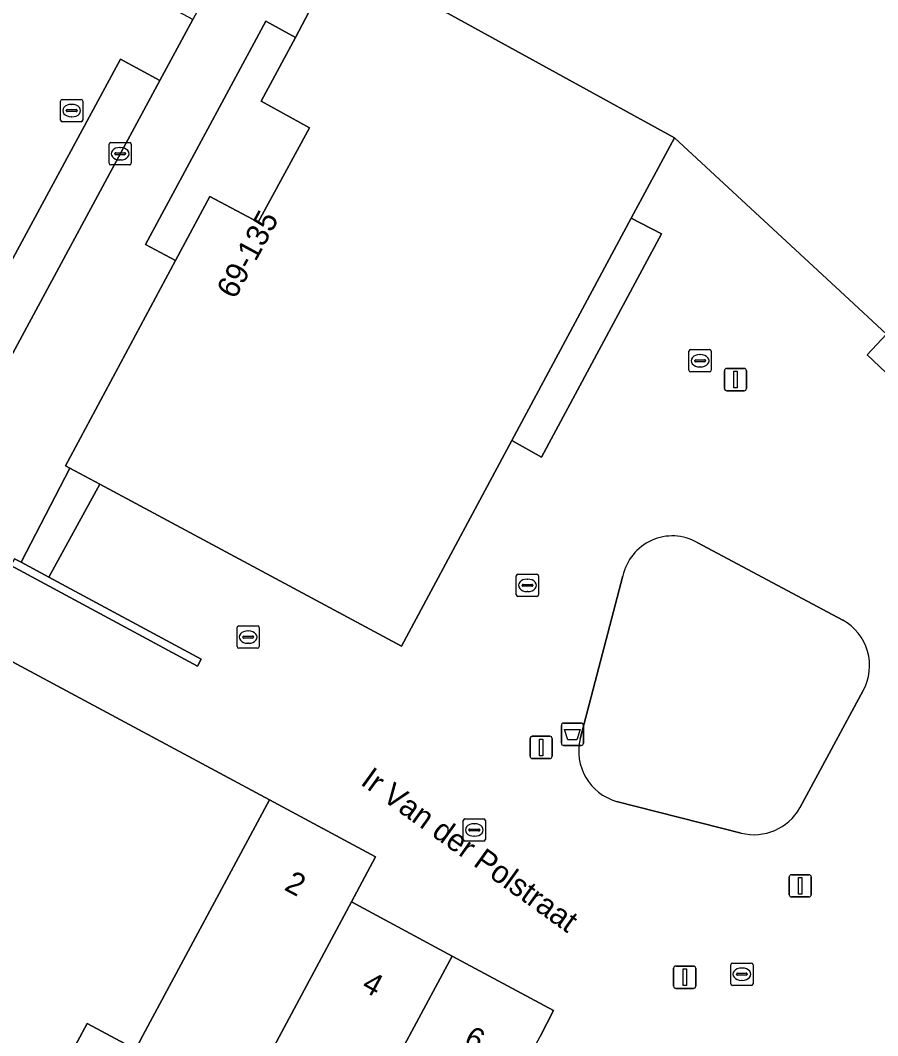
# Model space of a CAD drawing. Extents: x 159489 to 160304, y 383825 to 384531.
# Drawn here: x 159768.87 to 159807.43, y 384093.22 to 384138.89 of the extents above; entities that cross this region are included whole.
import ezdxf

# ---------------------------------------------------------------- set-up
doc = ezdxf.new("R2010")
doc.units = 0
for name, color, linetype in [('IMGEO_Afvalbak', 7, 'Continuous'), ('IMGEO_Erf', 7, 'Continuous'), ('IMGEO_Groenvoorziening', 7, 'Continuous'), ('IMGEO_Kolk', 7, 'Continuous'), ('IMGEO_Lichtmast', 7, 'Continuous'), ('IMGEO_Muur', 7, 'Continuous'), ('IMGEO_Openbare_ruimte_label', 7, 'Continuous'), ('IMGEO_Pand', 7, 'Continuous'), ('IMGEO_Pand_nummerreeks', 7, 'Continuous'), ('IMGEO_Pand_overbouw', 7, 'Continuous'), ('IMGEO_Parkeervlak_gesloten', 7, 'Continuous'), ('IMGEO_Rijbaan_lokaal_gesloten', 7, 'Continuous'), ('IMGEO_Rioolput', 7, 'Continuous'), ('IMGEO_Voetpad_open', 7, 'Continuous')]:
    doc.layers.add(name, color=color, linetype=linetype)

msp = doc.modelspace()

# ---------------------------------------------------------------- linework, layer by layer
at = {"layer": 'IMGEO_Afvalbak'}
for p, q in [((159793.2, 384106.378), (159793.2, 384107.178)), ((159793.2, 384107.178), (159793.2, 384106.378)), ((159793.3, 384107.278), (159794.09, 384107.278)), ((159794.09, 384107.278), (159793.3, 384107.278)), ((159794.19, 384107.178), (159794.19, 384106.378)), ((159794.19, 384106.378), (159794.19, 384107.178)), ((159794.09, 384106.278), (159793.3, 384106.278)), ((159793.3, 384106.278), (159794.09, 384106.278))]:
    msp.add_line(p, q, dxfattribs=at)
msp.add_lwpolyline([(159793.343, 384106.992), (159794.047, 384106.992), (159793.898, 384106.522), (159793.492, 384106.522), (159793.343, 384106.992)], dxfattribs=at)
for centre, start, end in [((159793.3, 384107.178), 90, 180), ((159793.3, 384107.178), 90, 180), ((159794.09, 384107.178), 0, 90), ((159794.09, 384107.178), 360, 90), ((159793.3, 384106.378), 180, 270), ((159793.3, 384106.378), 180, 270), ((159794.09, 384106.378), 270, 0), ((159794.09, 384106.378), 270, 0)]:
    msp.add_arc(centre, 0.1, start, end, dxfattribs=at)
at = {"layer": 'IMGEO_Erf'}
msp.add_lwpolyline([(159773.584, 384092.86), (159771.882, 384093.775), (159768.398, 384087.297)], dxfattribs=at)
at = {"layer": 'IMGEO_Groenvoorziening'}
for points in [[(159805.852, 384111.908), (159799.312, 384115.406)], [(159795.969, 384113.899), (159794.052, 384106.576)], [(159803.924, 384103.465), (159806.774, 384108.74)], [(159795.687, 384103.761), (159801.284, 384102.333)]]:
    msp.add_lwpolyline(points, dxfattribs=at)
for centre, radius, start, end in [((159798.195, 384113.423), 2.276, 60.5947, 167.9364), ((159804.736, 384109.865), 2.328, 331.1022, 61.3515), ((159796.32, 384106.011), 2.338, 166.0161, 254.2814), ((159801.862, 384104.63), 2.368, 255.8778, 330.5404)]:
    msp.add_arc(centre, radius, start, end, dxfattribs=at)
at = {"layer": 'IMGEO_Kolk'}
for p, q in [((159772.935, 384133.386), (159773.787, 384133.386)), ((159772.86, 384132.46), (159772.86, 384133.312)), ((159773.119, 384132.88), (159773.119, 384132.892)), ((159773.162, 384132.929), (159773.56, 384132.929)), ((159773.348, 384133.166), (159773.373, 384133.166)), ((159773.603, 384132.892), (159773.603, 384132.88)), ((159773.861, 384133.312), (159773.861, 384132.46)), ((159773.557, 384132.843), (159773.159, 384132.843)), ((159773.371, 384132.606), (159773.346, 384132.606)), ((159773.787, 384132.386), (159772.935, 384132.386)), ((159798.939, 384123.15), (159798.939, 384124.002)), ((159799.014, 384124.076), (159799.866, 384124.076)), ((159799.427, 384123.856), (159799.452, 384123.856)), ((159799.94, 384124.002), (159799.94, 384123.15)), ((159799.198, 384123.57), (159799.198, 384123.582)), ((159799.636, 384123.533), (159799.238, 384123.533)), ((159799.241, 384123.619), (159799.639, 384123.619)), ((159799.45, 384123.296), (159799.425, 384123.296)), ((159799.682, 384123.582), (159799.682, 384123.57)), ((159799.866, 384123.076), (159799.014, 384123.076)), ((159791.175, 384113.049), (159791.175, 384113.901)), ((159791.25, 384113.975), (159792.102, 384113.975)), ((159791.663, 384113.755), (159791.688, 384113.755)), ((159792.176, 384113.901), (159792.176, 384113.049)), ((159791.434, 384113.469), (159791.434, 384113.481)), ((159791.872, 384113.432), (159791.474, 384113.432)), ((159791.477, 384113.518), (159791.875, 384113.518)), ((159791.918, 384113.481), (159791.918, 384113.469)), ((159792.102, 384112.975), (159791.25, 384112.975)), ((159791.686, 384113.195), (159791.661, 384113.195)), ((159778.616, 384110.723), (159778.616, 384111.575)), ((159778.691, 384111.649), (159779.543, 384111.649)), ((159779.104, 384111.429), (159779.129, 384111.429)), ((159779.617, 384111.575), (159779.617, 384110.723)), ((159778.875, 384111.143), (159778.875, 384111.155)), ((159779.313, 384111.106), (159778.915, 384111.106)), ((159778.918, 384111.192), (159779.316, 384111.192)), ((159779.359, 384111.155), (159779.359, 384111.143)), ((159779.543, 384110.649), (159778.691, 384110.649)), ((159779.127, 384110.869), (159779.102, 384110.869)), ((159788.785, 384102.048), (159788.785, 384102.9)), ((159788.86, 384102.974), (159789.712, 384102.974)), ((159789.273, 384102.754), (159789.298, 384102.754)), ((159789.786, 384102.9), (159789.786, 384102.048)), ((159789.044, 384102.468), (159789.044, 384102.48)), ((159789.482, 384102.431), (159789.084, 384102.431)), ((159789.087, 384102.517), (159789.485, 384102.517)), ((159789.528, 384102.48), (159789.528, 384102.468)), ((159789.712, 384101.974), (159788.86, 384101.974)), ((159789.296, 384102.194), (159789.271, 384102.194)), ((159800.819, 384095.561), (159800.819, 384096.413)), ((159800.894, 384096.487), (159801.746, 384096.487)), ((159801.82, 384096.413), (159801.82, 384095.561)), ((159801.078, 384095.981), (159801.078, 384095.993)), ((159801.516, 384095.944), (159801.118, 384095.944)), ((159801.121, 384096.03), (159801.519, 384096.03)), ((159801.307, 384096.267), (159801.332, 384096.267)), ((159801.562, 384095.993), (159801.562, 384095.981)), ((159801.746, 384095.487), (159800.894, 384095.487)), ((159801.33, 384095.707), (159801.305, 384095.707))]:
    msp.add_line(p, q, dxfattribs=at)
for points in [[(159772.935, 384133.386), (159773.787, 384133.386)], [(159772.86, 384132.46), (159772.86, 384133.312)], [(159773.861, 384133.312), (159773.861, 384132.46)], [(159773.787, 384132.386), (159772.935, 384132.386)], [(159798.939, 384123.15), (159798.939, 384124.002)], [(159799.014, 384124.076), (159799.866, 384124.076)], [(159799.94, 384124.002), (159799.94, 384123.15)], [(159799.866, 384123.076), (159799.014, 384123.076)], [(159791.175, 384113.049), (159791.175, 384113.901)], [(159791.25, 384113.975), (159792.102, 384113.975)], [(159792.176, 384113.901), (159792.176, 384113.049)], [(159792.102, 384112.975), (159791.25, 384112.975)], [(159778.616, 384110.723), (159778.616, 384111.575)], [(159778.691, 384111.649), (159779.543, 384111.649)], [(159779.617, 384111.575), (159779.617, 384110.723)], [(159779.543, 384110.649), (159778.691, 384110.649)], [(159788.785, 384102.048), (159788.785, 384102.9)], [(159788.86, 384102.974), (159789.712, 384102.974)], [(159789.786, 384102.9), (159789.786, 384102.048)], [(159789.712, 384101.974), (159788.86, 384101.974)], [(159800.819, 384095.561), (159800.819, 384096.413)], [(159800.894, 384096.487), (159801.746, 384096.487)], [(159801.82, 384096.413), (159801.82, 384095.561)], [(159801.746, 384095.487), (159800.894, 384095.487)]]:
    msp.add_lwpolyline(points, dxfattribs=at)
for centre, radius, start, end in [((159772.937, 384133.31), 0.0765, 91.552, 178.448), ((159772.937, 384133.31), 0.0765, 91.552, 178.448), ((159773.785, 384133.31), 0.0765, 1.552, 88.448), ((159773.785, 384133.31), 0.0765, 1.552, 88.448), ((159773.159, 384132.889), 0.0403, 85.8775, 175.7526), ((159773.156, 384132.879), 0.0366, 178.938, 274.7102), ((159773.56, 384132.886), 0.043, 264.8664, 352.4533), ((159773.564, 384132.891), 0.0386, 1.7309, 96.639), ((159772.937, 384132.462), 0.0765, 181.552, 268.448), ((159772.937, 384132.462), 0.0765, 181.552, 268.448), ((159773.785, 384132.462), 0.0765, 271.552, 358.448), ((159773.785, 384132.462), 0.0765, 271.552, 358.448), ((159799.016, 384124), 0.0765, 91.552, 178.448), ((159799.016, 384124), 0.0765, 91.552, 178.448), ((159799.864, 384124), 0.0765, 1.552, 88.448), ((159799.864, 384124), 0.0765, 1.552, 88.448), ((159799.238, 384123.579), 0.0403, 85.8775, 175.7526), ((159799.235, 384123.569), 0.0366, 178.938, 274.7102), ((159799.639, 384123.576), 0.043, 264.8664, 352.4533), ((159799.643, 384123.581), 0.0386, 1.7309, 96.639), ((159799.016, 384123.152), 0.0765, 181.552, 268.448), ((159799.016, 384123.152), 0.0765, 181.552, 268.448), ((159799.864, 384123.152), 0.0765, 271.552, 358.448), ((159799.864, 384123.152), 0.0765, 271.552, 358.448), ((159791.252, 384113.899), 0.0765, 91.552, 178.448), ((159791.252, 384113.899), 0.0765, 91.552, 178.448), ((159792.1, 384113.899), 0.0765, 1.552, 88.448), ((159792.1, 384113.899), 0.0765, 1.552, 88.448), ((159791.474, 384113.478), 0.0403, 85.8775, 175.7526), ((159791.471, 384113.468), 0.0366, 178.938, 274.7102), ((159791.875, 384113.475), 0.043, 264.8664, 352.4533), ((159791.879, 384113.48), 0.0386, 1.7309, 96.639), ((159791.252, 384113.051), 0.0765, 181.552, 268.448), ((159791.252, 384113.051), 0.0765, 181.552, 268.448), ((159792.1, 384113.051), 0.0765, 271.552, 358.448), ((159792.1, 384113.051), 0.0765, 271.552, 358.448), ((159778.693, 384111.573), 0.0765, 91.552, 178.448), ((159778.693, 384111.573), 0.0765, 91.552, 178.448), ((159779.541, 384111.573), 0.0765, 1.552, 88.448), ((159779.541, 384111.573), 0.0765, 1.552, 88.448), ((159778.915, 384111.152), 0.0403, 85.8775, 175.7526), ((159778.912, 384111.142), 0.0366, 178.938, 274.7102), ((159779.316, 384111.149), 0.043, 264.8664, 352.4533), ((159779.32, 384111.154), 0.0386, 1.7309, 96.639), ((159778.693, 384110.725), 0.0765, 181.552, 268.448), ((159778.693, 384110.725), 0.0765, 181.552, 268.448), ((159779.541, 384110.725), 0.0765, 271.552, 358.448), ((159779.541, 384110.725), 0.0765, 271.552, 358.448), ((159788.862, 384102.898), 0.0765, 91.552, 178.448), ((159788.862, 384102.898), 0.0765, 91.552, 178.448), ((159789.71, 384102.898), 0.0765, 1.552, 88.448), ((159789.71, 384102.898), 0.0765, 1.552, 88.448), ((159789.084, 384102.477), 0.0403, 85.8775, 175.7526), ((159789.081, 384102.467), 0.0366, 178.938, 274.7102), ((159789.485, 384102.474), 0.043, 264.8664, 352.4533), ((159789.489, 384102.479), 0.0386, 1.7309, 96.639), ((159788.862, 384102.05), 0.0765, 181.552, 268.448), ((159788.862, 384102.05), 0.0765, 181.552, 268.448), ((159789.71, 384102.05), 0.0765, 271.552, 358.448), ((159789.71, 384102.05), 0.0765, 271.552, 358.448), ((159800.896, 384096.411), 0.0765, 91.552, 178.448), ((159800.896, 384096.411), 0.0765, 91.552, 178.448), ((159801.744, 384096.411), 0.0765, 1.552, 88.448), ((159801.744, 384096.411), 0.0765, 1.552, 88.448), ((159801.118, 384095.99), 0.0403, 85.8775, 175.7526), ((159801.115, 384095.98), 0.0366, 178.938, 274.7102), ((159801.519, 384095.987), 0.043, 264.8664, 352.4533), ((159801.523, 384095.992), 0.0386, 1.7309, 96.639), ((159800.896, 384095.563), 0.0765, 181.552, 268.448), ((159800.896, 384095.563), 0.0765, 181.552, 268.448), ((159801.744, 384095.563), 0.0765, 271.552, 358.448), ((159801.744, 384095.563), 0.0765, 271.552, 358.448)]:
    msp.add_arc(centre, radius, start, end, dxfattribs=at)
for centre, major_axis, ratio, start_param, end_param in [((159773.347, 384132.886), (-0.387, 0.002), 0.722429, 4.712389, 7.853982), ((159773.372, 384132.886), (-0.39, 0.002), 0.717154, 1.570796, 4.712389), ((159799.426, 384123.576), (-0.387, 0.002), 0.722429, 4.712389, 7.853982), ((159799.451, 384123.576), (-0.39, 0.002), 0.717154, 1.570796, 4.712389), ((159791.662, 384113.475), (-0.387, 0.002), 0.722429, 4.712389, 7.853982), ((159791.687, 384113.475), (-0.39, 0.002), 0.717154, 1.570796, 4.712389), ((159779.103, 384111.149), (-0.387, 0.002), 0.722429, 4.712389, 7.853982), ((159779.128, 384111.149), (-0.39, 0.002), 0.717154, 1.570796, 4.712389), ((159789.272, 384102.474), (-0.387, 0.002), 0.722429, 4.712389, 7.853982), ((159789.297, 384102.474), (-0.39, 0.002), 0.717154, 1.570796, 4.712389), ((159801.306, 384095.987), (-0.387, 0.002), 0.722429, 4.712389, 7.853982), ((159801.331, 384095.987), (-0.39, 0.002), 0.717154, 1.570796, 4.712389)]:
    msp.add_ellipse(centre, major_axis=major_axis, ratio=ratio, start_param=start_param, end_param=end_param, dxfattribs=at)
at = {"layer": 'IMGEO_Lichtmast'}
for p, q in [((159800.536, 384122.33), (159800.536, 384123.13)), ((159800.536, 384123.13), (159800.536, 384122.33)), ((159800.636, 384123.23), (159801.426, 384123.23)), ((159801.426, 384123.23), (159800.636, 384123.23)), ((159801.526, 384123.13), (159801.526, 384122.33)), ((159801.526, 384122.33), (159801.526, 384123.13)), ((159801.426, 384122.23), (159800.636, 384122.23)), ((159800.636, 384122.23), (159801.426, 384122.23)), ((159791.794, 384105.786), (159791.794, 384106.586)), ((159791.794, 384106.586), (159791.794, 384105.786)), ((159791.894, 384106.686), (159792.684, 384106.686)), ((159792.684, 384106.686), (159791.894, 384106.686)), ((159792.784, 384106.586), (159792.784, 384105.786)), ((159792.784, 384105.786), (159792.784, 384106.586)), ((159792.684, 384105.686), (159791.894, 384105.686)), ((159791.894, 384105.686), (159792.684, 384105.686)), ((159803.545, 384100.463), (159804.335, 384100.463)), ((159804.335, 384100.463), (159803.545, 384100.463)), ((159803.445, 384099.563), (159803.445, 384100.363)), ((159803.445, 384100.363), (159803.445, 384099.563)), ((159804.435, 384100.363), (159804.435, 384099.563)), ((159804.435, 384099.563), (159804.435, 384100.363)), ((159804.335, 384099.463), (159803.545, 384099.463)), ((159803.545, 384099.463), (159804.335, 384099.463)), ((159798.351, 384096.352), (159799.141, 384096.352)), ((159799.141, 384096.352), (159798.351, 384096.352)), ((159798.251, 384095.452), (159798.251, 384096.252)), ((159798.251, 384096.252), (159798.251, 384095.452)), ((159799.241, 384096.252), (159799.241, 384095.452)), ((159799.241, 384095.452), (159799.241, 384096.252)), ((159799.141, 384095.352), (159798.351, 384095.352)), ((159798.351, 384095.352), (159799.141, 384095.352))]:
    msp.add_line(p, q, dxfattribs=at)
for points in [[(159800.956, 384123.105), (159801.106, 384123.105), (159801.106, 384122.355), (159800.956, 384122.355), (159800.956, 384123.105)], [(159792.214, 384106.561), (159792.364, 384106.561), (159792.364, 384105.811), (159792.214, 384105.811), (159792.214, 384106.561)], [(159803.865, 384100.338), (159804.015, 384100.338), (159804.015, 384099.588), (159803.865, 384099.588), (159803.865, 384100.338)], [(159798.671, 384096.227), (159798.821, 384096.227), (159798.821, 384095.477), (159798.671, 384095.477), (159798.671, 384096.227)]]:
    msp.add_lwpolyline(points, dxfattribs=at)
for centre, start, end in [((159800.636, 384123.13), 90, 180), ((159800.636, 384123.13), 90, 180), ((159801.426, 384123.13), 0, 90), ((159801.426, 384123.13), 360, 90), ((159800.636, 384122.33), 180, 270), ((159800.636, 384122.33), 180, 270), ((159801.426, 384122.33), 270, 0), ((159801.426, 384122.33), 270, 0), ((159791.894, 384106.586), 90, 180), ((159791.894, 384106.586), 90, 180), ((159792.684, 384106.586), 0, 90), ((159792.684, 384106.586), 360, 90), ((159791.894, 384105.786), 180, 270), ((159791.894, 384105.786), 180, 270), ((159792.684, 384105.786), 270, 0), ((159792.684, 384105.786), 270, 0), ((159803.545, 384100.363), 90, 180), ((159803.545, 384100.363), 90, 180), ((159804.335, 384100.363), 0, 90), ((159804.335, 384100.363), 360, 90), ((159803.545, 384099.563), 180, 270), ((159803.545, 384099.563), 180, 270), ((159804.335, 384099.563), 270, 0), ((159804.335, 384099.563), 270, 0), ((159798.351, 384096.252), 90, 180), ((159798.351, 384096.252), 90, 180), ((159799.141, 384096.252), 0, 90), ((159799.141, 384096.252), 360, 90), ((159798.351, 384095.452), 180, 270), ((159798.351, 384095.452), 180, 270), ((159799.141, 384095.452), 270, 0), ((159799.141, 384095.452), 270, 0)]:
    msp.add_arc(centre, 0.1, start, end, dxfattribs=at)
at = {"layer": 'IMGEO_Muur'}
msp.add_lwpolyline([(159768.906, 384114.514), (159768.611, 384114.673), (159768.446, 384114.365), (159776.835, 384109.843), (159777.002, 384110.151), (159770.147, 384113.845)], close=True, dxfattribs=at)
at = {"layer": 'IMGEO_Pand'}
for points in [[(159836.006, 384134.084), (159837.566, 384133.683), (159839.222, 384140.129), (159819.699, 384150.609), (159819.305, 384150.823), (159814.929, 384153.207), (159799.236, 384161.615), (159795.062, 384163.855), (159786.151, 384147.266), (159783.227, 384141.884), (159798.285, 384133.608), (159806.143, 384126.329), (159807.826, 384124.77), (159812.12, 384120.793), (159813.7, 384120.358), (159816.6, 384119.612), (159818.956, 384127.743), (159834.974, 384123.654), (159835.035, 384123.895), (159836.385, 384129.134), (159834.836, 384129.507)], [(159798.285, 384133.608), (159783.227, 384141.884), (159781.249, 384138.115), (159779.704, 384135.243), (159781.88, 384134.044), (159779.568, 384129.802), (159777.398, 384130.962), (159775.853, 384128.086), (159770.9, 384118.851), (159771.098, 384118.744), (159772.445, 384118.022), (159786.016, 384110.746), (159790.975, 384119.986), (159796.346, 384129.995)], [(159780.079, 384103.825), (159766.66, 384111.026), (159765.061, 384108.041), (159763.74, 384105.588), (159763.585, 384104.945), (159761.091, 384100.297), (159760.941, 384100.377), (159757.19, 384093.409), (159767.715, 384087.664), (159768.398, 384087.297), (159771.882, 384093.775), (159773.584, 384092.86), (159774.052, 384092.608), (159774.383, 384093.224)], [(159783.759, 384099.239), (159784.844, 384101.268), (159780.079, 384103.825), (159774.383, 384093.224), (159774.052, 384092.608), (159773.584, 384092.86), (159772.986, 384091.747), (159778.243, 384088.92), (159779.168, 384090.651)], [(159788.289, 384096.804), (159783.759, 384099.239), (159779.168, 384090.651), (159778.243, 384088.92), (159782.746, 384086.499), (159783.685, 384088.244)], [(159792.249, 384093.193), (159792.852, 384094.351), (159788.289, 384096.804), (159783.685, 384088.244), (159782.746, 384086.499), (159787.322, 384084.039), (159788.25, 384085.766)]]:
    msp.add_lwpolyline(points, close=True, dxfattribs=at)
at = {"layer": 'IMGEO_Pand_overbouw'}
for points in [[(159775.853, 384128.086), (159777.398, 384130.962), (159779.568, 384129.802), (159781.88, 384134.044), (159779.704, 384135.243), (159781.249, 384138.115), (159779.906, 384138.843), (159774.496, 384128.807)], [(159790.975, 384119.986), (159792.304, 384119.236), (159797.698, 384129.277), (159796.346, 384129.995)]]:
    msp.add_lwpolyline(points, close=True, dxfattribs=at)
at = {"layer": 'IMGEO_Parkeervlak_gesloten'}
msp.add_lwpolyline([(159775.147, 384136.187), (159773.371, 384137.146), (159765.302, 384122.213), (159767.077, 384121.254)], close=True, dxfattribs=at)
at = {"layer": 'IMGEO_Rijbaan_lokaal_gesloten'}
msp.add_lwpolyline([(159764.983, 384117.379), (159767.077, 384121.254), (159765.302, 384122.213), (159773.371, 384137.146), (159775.147, 384136.187), (159776.629, 384138.93), (159774.854, 384139.889), (159777.432, 384144.66), (159779.207, 384143.701), (159782.562, 384149.935), (159784.449, 384153.458), (159782.671, 384154.411), (159787.869, 384164.115), (159789.648, 384163.162), (159791.147, 384165.96), (159791.589, 384166.785)], dxfattribs=at)
at = {"layer": 'IMGEO_Rioolput'}
for p, q in [((159770.678, 384134.4), (159770.678, 384135.252)), ((159770.753, 384135.326), (159771.605, 384135.326)), ((159771.679, 384135.252), (159771.679, 384134.4)), ((159770.937, 384134.82), (159770.937, 384134.832)), ((159771.375, 384134.783), (159770.977, 384134.783)), ((159770.98, 384134.869), (159771.378, 384134.869)), ((159771.166, 384135.106), (159771.191, 384135.106)), ((159771.421, 384134.832), (159771.421, 384134.82)), ((159771.605, 384134.326), (159770.753, 384134.326)), ((159771.189, 384134.546), (159771.164, 384134.546))]:
    msp.add_line(p, q, dxfattribs=at)
for points in [[(159770.678, 384134.4), (159770.678, 384135.252)], [(159770.753, 384135.326), (159771.605, 384135.326)], [(159771.679, 384135.252), (159771.679, 384134.4)], [(159771.605, 384134.326), (159770.753, 384134.326)]]:
    msp.add_lwpolyline(points, dxfattribs=at)
for centre, radius, start, end in [((159770.755, 384135.25), 0.0765, 91.552, 178.448), ((159770.755, 384135.25), 0.0765, 91.552, 178.448), ((159771.603, 384135.25), 0.0765, 1.552, 88.448), ((159771.603, 384135.25), 0.0765, 1.552, 88.448), ((159770.977, 384134.829), 0.0403, 85.8775, 175.7526), ((159770.974, 384134.819), 0.0366, 178.938, 274.7102), ((159771.378, 384134.826), 0.043, 264.8664, 352.4533), ((159771.382, 384134.831), 0.0386, 1.7309, 96.639), ((159770.755, 384134.402), 0.0765, 181.552, 268.448), ((159770.755, 384134.402), 0.0765, 181.552, 268.448), ((159771.603, 384134.402), 0.0765, 271.552, 358.448), ((159771.603, 384134.402), 0.0765, 271.552, 358.448)]:
    msp.add_arc(centre, radius, start, end, dxfattribs=at)
for centre, major_axis, ratio, start_param, end_param in [((159771.165, 384134.826), (-0.387, 0.002), 0.722429, 4.712389, 7.853982), ((159771.19, 384134.826), (-0.39, 0.002), 0.717154, 1.570796, 4.712389)]:
    msp.add_ellipse(centre, major_axis=major_axis, ratio=ratio, start_param=start_param, end_param=end_param, dxfattribs=at)
at = {"layer": 'IMGEO_Voetpad_open'}
for points in [[(159768.611, 384114.673), (159768.906, 384114.514), (159771.098, 384118.744), (159770.9, 384118.851), (159775.853, 384128.086), (159774.496, 384128.807), (159779.906, 384138.843), (159781.249, 384138.115), (159783.227, 384141.884), (159786.151, 384147.266), (159785.194, 384147.8), (159794.091, 384164.365), (159791.147, 384165.96), (159789.648, 384163.162), (159784.449, 384153.458), (159782.562, 384149.935), (159783.314, 384149.478), (159779.992, 384143.271), (159779.207, 384143.701), (159776.629, 384138.93), (159775.147, 384136.187), (159767.077, 384121.254)], [(159809.159, 384090.473), (159814.676, 384112.061), (159815.881, 384116.79), (159816.6, 384119.612), (159813.7, 384120.358), (159812.12, 384120.793), (159811.179, 384119.845), (159806.946, 384123.837), (159807.826, 384124.77), (159806.143, 384126.329), (159798.285, 384133.608), (159796.346, 384129.995), (159797.698, 384129.277), (159792.304, 384119.236), (159790.975, 384119.986), (159786.016, 384110.746), (159772.445, 384118.022), (159770.147, 384113.845), (159777.002, 384110.151), (159776.835, 384109.843), (159768.446, 384114.365)], [(159799.312, 384115.406), (159805.852, 384111.908)], [(159794.052, 384106.576), (159795.969, 384113.899)], [(159766.66, 384111.026), (159780.079, 384103.825), (159784.844, 384101.268), (159783.759, 384099.239), (159788.289, 384096.804), (159792.852, 384094.351), (159792.249, 384093.193)], [(159806.774, 384108.74), (159803.924, 384103.465)], [(159801.284, 384102.333), (159795.687, 384103.761)]]:
    msp.add_lwpolyline(points, dxfattribs=at)
for points in [[(159779.906, 384138.843), (159774.496, 384128.807), (159775.853, 384128.086), (159777.398, 384130.962), (159779.568, 384129.802), (159781.88, 384134.044), (159779.704, 384135.243), (159781.249, 384138.115)], [(159792.304, 384119.236), (159797.698, 384129.277), (159796.346, 384129.995), (159790.975, 384119.986)], [(159806.946, 384123.837), (159811.179, 384119.845), (159812.12, 384120.793), (159807.826, 384124.77)], [(159770.147, 384113.845), (159772.445, 384118.022), (159771.098, 384118.744), (159768.906, 384114.514)]]:
    msp.add_lwpolyline(points, close=True, dxfattribs=at)
for centre, radius, start, end in [((159798.195, 384113.423), 2.276, 60.5947, 167.9364), ((159804.736, 384109.865), 2.328, 331.1022, 61.3515), ((159796.32, 384106.011), 2.338, 166.0161, 254.2814), ((159801.862, 384104.63), 2.368, 255.8778, 330.5404)]:
    msp.add_arc(centre, radius, start, end, dxfattribs=at)

# ---------------------------------------------------------------- texts
at = {"layer": 'IMGEO_Openbare_ruimte_label'}
msp.add_text('Ir Van der Polstraat', height=1, rotation=324.2759, dxfattribs=at).set_placement((159784.122, 384104.549))
at = {"layer": 'IMGEO_Pand_nummerreeks'}
for s, rotation, p in [('69-135', 61.3972, (159778.522, 384126.305)), ('2', 332.1371, (159780.691, 384099.802)), ('4', 331.312, (159784.166, 384095.297)), ('6', 332.3204, (159788.751, 384092.823))]:
    msp.add_text(s, height=1, rotation=rotation, dxfattribs=at).set_placement(p)

doc.saveas('drawing.dxf')
